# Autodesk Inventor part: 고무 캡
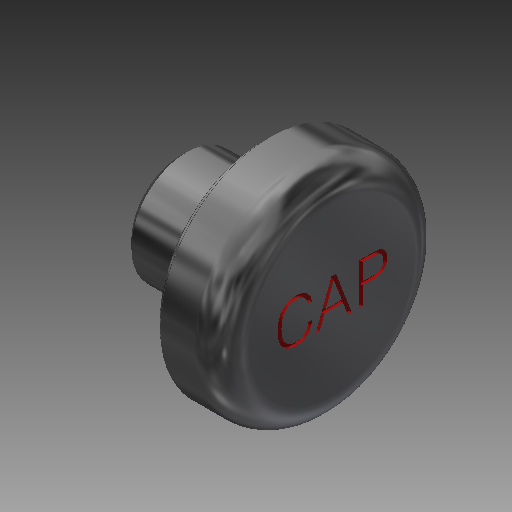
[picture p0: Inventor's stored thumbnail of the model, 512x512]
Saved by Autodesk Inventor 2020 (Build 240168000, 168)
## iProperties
Created: 2017-06
Part Number: 고무 캡
Material: 고무
Document SubType Name: Modeling
Designer: mduedu
Density: 1 g/cm^3
Appearance: 고무 - 검은색 - 버전 1.1
Author: mduedu
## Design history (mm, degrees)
sketch "스케치1"
  geometry: L1 (0, 0)-(11, 0); L2 (11, 0)-(11, 8); L3 (11, 8)-(6.5, 8); L4 (0, 4)-(0, 0); L5 (0, 4)-(6, 4); L6 (6, 4)-(6, 7.5); L7 (6, 7.5)-(6.5, 7.5); L8 (6.5, 7.5)-(6.5, 8)
  constraints: 16 end point, 2 horizontal, 2 parallel, 2 perpendicular, 2 point on line, 1 vertical
  dimensions: "d0" = 16 diameter of L3 L1; "d2" = 8 diameter of L5 L1; "d6" = 5 distance between parallel lines of L2 L6; "d7" = 0.5 distance between parallel lines of L8 L6; "d8" = 15 diameter of L7 L1; "d9" = 6 distance between parallel lines of L6 L4
revolve "회전1" sketch "스케치1" stored, may be unused: angle "d10" = 90 deg
hole "구멍1" diameter "d22" = 5; stored, may be unused: countersink angle "d26" = 90 deg, drill point angle "d28" = 0 deg; dims "d23" = 6, "d24" = 4, "d25" = 2, "d27" = 6, "d30" = 10, "d31" = 10
chamfer "모따기1" distance "d13" = 0.5; stored, may be unused: second distance "d14" = 2, angle "d15" = 45 deg
fillet "모깎기3" dims "d29" = 1
fillet "모깎기1" dims "d16" = 0.1
fillet "모깎기2" dims "d17" = 2
sketch "스케치3"
  geometry: 2 further points
  constraints: 1 coincident, 1 other
feature "엠보싱1" sketch "스케치3" dims "d16" = 0.1, "d18" = 0.2, "d19" = 0
node "솔리드1"
